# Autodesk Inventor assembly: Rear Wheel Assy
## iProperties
Length Units: 11269
Angle Units: 11279
Time Units: 11290
Mass Units: 11283
Shininess: 3
Angle Display Precision: 2
Document Length Units: 11269
Document Angle Units: 11279
Document Time Units: 11290
Document Mass Units: 11283
Document Length Units Precision: 3
Document Angle Units Precision: 2
Compacted: True
Created: 2001-08
Part Number: Rear Wheel Assy
Document SubType Name: Assembly
Designer: rak
Description: Rear Wheel Assy
Density: 0.0
Volumn: 0.0
Area: 0.0
PropertySet Name: Model Information
Control State: 0
Master: False
Checked Out: False
Author: rak
